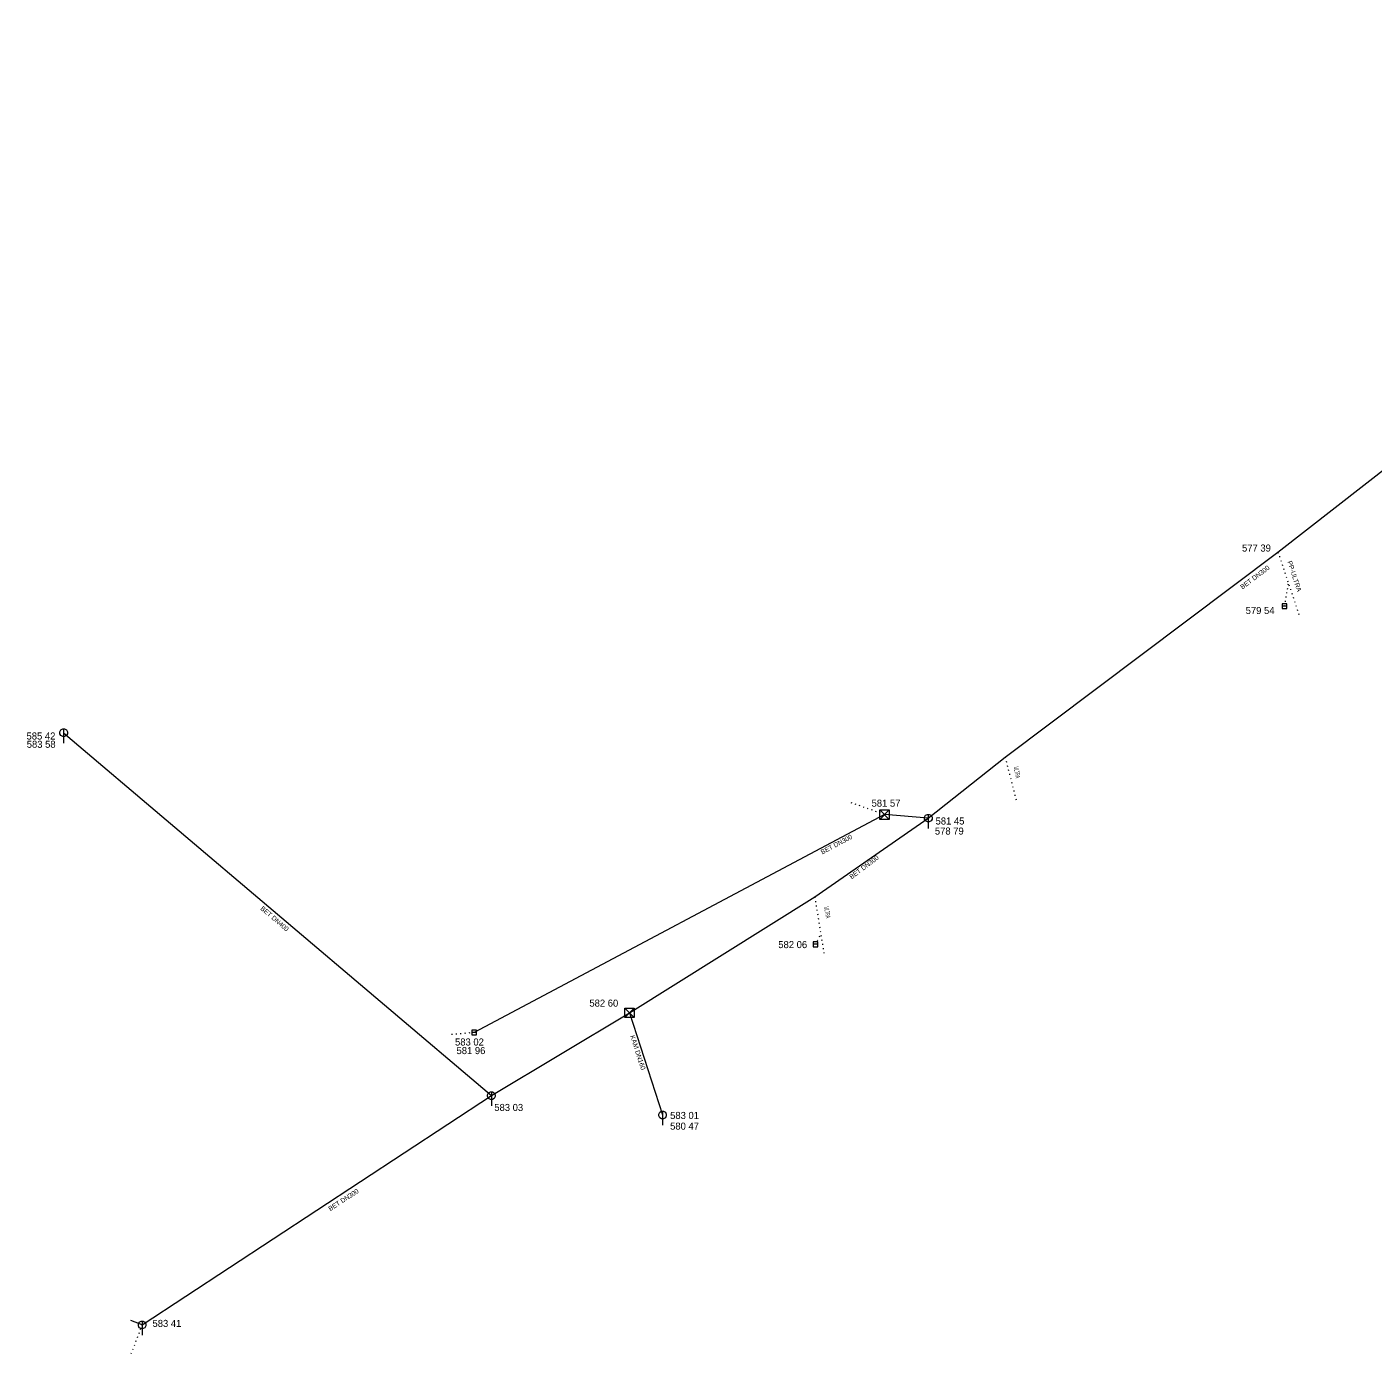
# Model space of a CAD drawing. Extents: x -710806 to -710046, y -1116920 to -1116046.
# Drawn here: x -710806 to -710662.8, y -1116919.9 to -1116778.5 of the extents above; entities that cross this region are included whole.
import ezdxf
from ezdxf.enums import TextEntityAlignment as Align

# ---------------------------------------------------------------- set-up
doc = ezdxf.new("R2010")
doc.units = 0
doc.header["$LTSCALE"] = 0.3
doc.linetypes.add('DOTTED', pattern=[1.5, 0.3, -1.2])
for name, color, linetype, lineweight in [('40', 7, 'Continuous', 13), ('41', 7, 'Continuous', 13), ('45', 7, 'DOTTED', 13)]:
    doc.layers.add(name, color=color, linetype=linetype, lineweight=lineweight)
doc.layers.add('43', color=7, linetype='Continuous')
doc.layers.add('44', color=7, linetype='Continuous')

msp = doc.modelspace()

# ---------------------------------------------------------------- linework, layer by layer
at = {"layer": '40'}
for p, q in [((-710802.145, -1116853.58), (-710756.639, -1116892.195)), ((-710793.793, -1116916.592), (-710794.983, -1116916.118))]:
    msp.add_line(p, q, dxfattribs=at)
for points in [[(-710710.163, -1116862.665), (-710701.994, -1116856.17), (-710672.966, -1116834.362), (-710648.579, -1116815.338), (-710637.958, -1116807.538), (-710603.228, -1116781.343), (-710606.681, -1116778.465), (-710610.837, -1116781.602), (-710650.875, -1116812.584)], [(-710741.962, -1116883.389), (-710722.241, -1116871.047), (-710710.163, -1116862.665), (-710714.81, -1116862.296), (-710758.476, -1116885.482)], [(-710793.793, -1116916.592), (-710756.639, -1116892.195), (-710741.962, -1116883.389), (-710738.435, -1116894.253)]]:
    msp.add_lwpolyline(points, dxfattribs=at)
at = {"layer": '41'}
for p, q in [((-710672.009, -1116839.85), (-710672.509, -1116839.85)), ((-710672.509, -1116839.85), (-710672.509, -1116840.35)), ((-710672.009, -1116840.35), (-710672.009, -1116839.85)), ((-710672.009, -1116840.1), (-710672.509, -1116840.1)), ((-710672.509, -1116840.35), (-710672.009, -1116840.35)), ((-710802.145, -1116853.18), (-710802.145, -1116854.68)), ((-710715.31, -1116861.796), (-710714.31, -1116862.796)), ((-710714.31, -1116861.796), (-710715.31, -1116862.796)), ((-710710.163, -1116862.265), (-710710.163, -1116863.765)), ((-710721.926, -1116875.846), (-710722.426, -1116875.846)), ((-710722.426, -1116875.846), (-710722.426, -1116876.346)), ((-710721.926, -1116876.096), (-710722.426, -1116876.096)), ((-710722.426, -1116876.346), (-710721.926, -1116876.346)), ((-710721.926, -1116876.346), (-710721.926, -1116875.846)), ((-710742.462, -1116882.889), (-710741.462, -1116883.889)), ((-710741.462, -1116882.889), (-710742.462, -1116883.889)), ((-710758.226, -1116885.232), (-710758.726, -1116885.232)), ((-710758.726, -1116885.232), (-710758.726, -1116885.732)), ((-710758.226, -1116885.482), (-710758.726, -1116885.482)), ((-710758.226, -1116885.732), (-710758.226, -1116885.232)), ((-710758.726, -1116885.732), (-710758.226, -1116885.732)), ((-710756.639, -1116891.795), (-710756.639, -1116893.295)), ((-710738.435, -1116893.853), (-710738.435, -1116895.353)), ((-710793.793, -1116916.192), (-710793.793, -1116917.692))]:
    msp.add_line(p, q, dxfattribs=at)
for points in [[(-710802.545, -1116853.68), (-710802.545, -1116853.48), (-710802.445, -1116853.28), (-710802.245, -1116853.18), (-710802.045, -1116853.18), (-710801.845, -1116853.28), (-710801.745, -1116853.48), (-710801.745, -1116853.68), (-710801.845, -1116853.88), (-710802.045, -1116853.98), (-710802.245, -1116853.98), (-710802.445, -1116853.88)], [(-710715.31, -1116861.796), (-710714.31, -1116861.796), (-710714.31, -1116862.796), (-710715.31, -1116862.796)], [(-710710.563, -1116862.765), (-710710.563, -1116862.565), (-710710.463, -1116862.365), (-710710.263, -1116862.265), (-710710.063, -1116862.265), (-710709.863, -1116862.365), (-710709.763, -1116862.565), (-710709.763, -1116862.765), (-710709.863, -1116862.965), (-710710.063, -1116863.065), (-710710.263, -1116863.065), (-710710.463, -1116862.965)], [(-710742.462, -1116882.889), (-710741.462, -1116882.889), (-710741.462, -1116883.889), (-710742.462, -1116883.889)], [(-710757.039, -1116892.295), (-710757.039, -1116892.095), (-710756.939, -1116891.895), (-710756.739, -1116891.795), (-710756.539, -1116891.795), (-710756.339, -1116891.895), (-710756.239, -1116892.095), (-710756.239, -1116892.295), (-710756.339, -1116892.495), (-710756.539, -1116892.595), (-710756.739, -1116892.595), (-710756.939, -1116892.495)], [(-710738.835, -1116894.353), (-710738.835, -1116894.153), (-710738.735, -1116893.953), (-710738.535, -1116893.853), (-710738.335, -1116893.853), (-710738.135, -1116893.953), (-710738.035, -1116894.153), (-710738.035, -1116894.353), (-710738.135, -1116894.553), (-710738.335, -1116894.653), (-710738.535, -1116894.653), (-710738.735, -1116894.553)], [(-710794.193, -1116916.692), (-710794.193, -1116916.492), (-710794.093, -1116916.292), (-710793.893, -1116916.192), (-710793.693, -1116916.192), (-710793.493, -1116916.292), (-710793.393, -1116916.492), (-710793.393, -1116916.692), (-710793.493, -1116916.892), (-710793.693, -1116916.992), (-710793.893, -1116916.992), (-710794.093, -1116916.892)]]:
    msp.add_lwpolyline(points, close=True, dxfattribs=at)
at = {"layer": '45'}
for p, q in [((-710672.966, -1116834.362), (-710670.692, -1116841.134)), ((-710672.259, -1116840.1), (-710671.844, -1116837.703)), ((-710701.994, -1116856.17), (-710700.761, -1116860.979)), ((-710714.81, -1116862.296), (-710718.573, -1116860.958)), ((-710722.241, -1116871.047), (-710721.23, -1116877.301)), ((-710722.176, -1116876.096), (-710721.599, -1116875.015)), ((-710758.476, -1116885.482), (-710761.022, -1116885.712)), ((-710793.793, -1116916.592), (-710795.073, -1116919.915))]:
    msp.add_line(p, q, dxfattribs=at)

# ---------------------------------------------------------------- texts
at = {"layer": '43'}
for s, p in [('577 39 ', (-710675.1162, -1116834.297)), ('579 54 ', (-710674.7292, -1116840.95)), ('585 42 ', (-710804.4162, -1116854.301)), ('581 57 ', (-710714.5242, -1116861.452)), ('581 45 ', (-710707.7162, -1116863.347)), ('582 06 ', (-710724.4462, -1116876.499)), ('582 60 ', (-710744.5412, -1116882.726)), ('583 02 ', (-710758.8342, -1116886.865)), ('583 03 ', (-710754.6562, -1116893.828)), ('583 01 ', (-710735.9532, -1116894.679)), ('583 41 ', (-710791.0172, -1116916.811))]:
    msp.add_text(s, height=0.75, dxfattribs=at).set_placement(p, align=Align.CENTER)
for s, p in [('583 58', (-710806.068, -1116855.18)), ('578 79', (-710709.464, -1116864.415)), ('581 96', (-710760.349, -1116887.779)), ('580 47', (-710737.628, -1116895.817))]:
    msp.add_text(s, height=0.75, dxfattribs=at).set_placement(p)
at = {"layer": '44'}
for s, rotation, p in [('PP-ULTRA', 288, (-710671.975, -1116835.38)), ('BET DN300', 36.9, (-710676.74, -1116838.336)), ('BET DN300', 27.9, (-710721.437, -1116866.537)), ('BET DN300', 36.9, (-710718.319, -1116869.19)), ('BET DN400', 319.5, (-710781.258, -1116872.361)), ('KAM DN160', 288, (-710741.883, -1116885.857)), ('BET DN300', 33.3, (-710773.776, -1116904.503))]:
    msp.add_text(s, height=0.5, rotation=rotation, dxfattribs=at).set_placement(p)
at = {"layer": '44', "width": 0.45}
for p in [(-710701.065, -1116857.225), (-710721.245, -1116872.127)]:
    msp.add_text('ULTRA', height=0.5, rotation=279, dxfattribs=at).set_placement(p)

doc.saveas('drawing.dxf')
